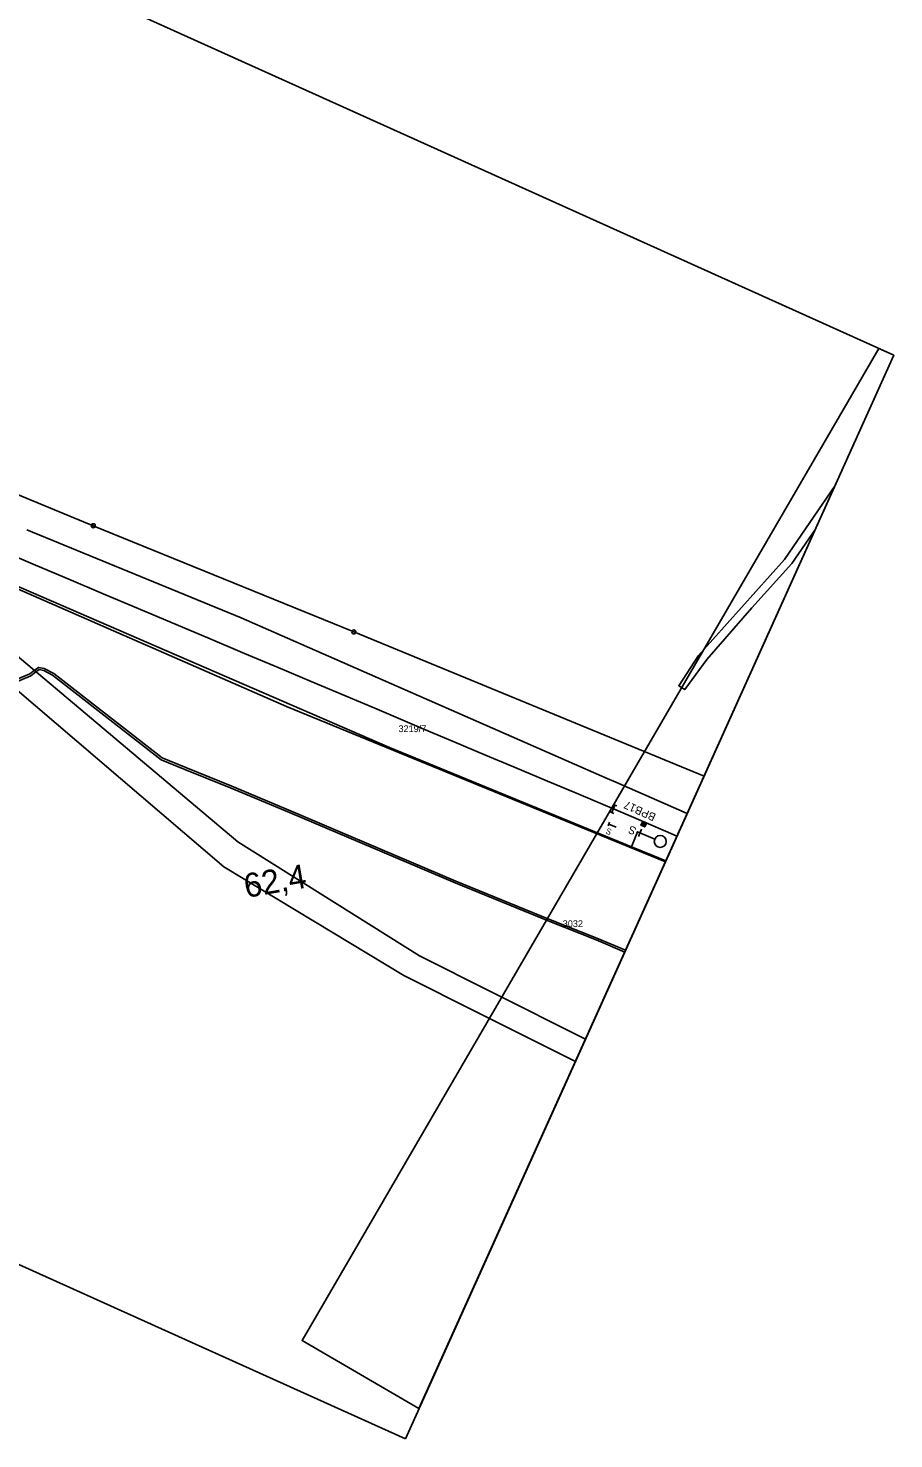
# Model space of a CAD drawing. Extents: x -621716 to -621020, y -1122350 to -1121821.
# Drawn here: x -621236.3 to -621020, y -1122350.4 to -1121998 of the extents above; entities that cross this region are included whole.
import ezdxf

# ---------------------------------------------------------------- set-up
doc = ezdxf.new("R2010")
doc.units = 0
for name, color, linetype in [('hm', 7, 'Continuous'), ('HranDP', 7, 'Continuous'), ('Hranice parcel', 7, 'Continuous'), ('Parcelní čísla', 7, 'Continuous'), ('Rámečky-tisk', 7, 'Continuous'), ('STANICENI NOVE HM', 7, 'Continuous'), ('Vrstva 1', 7, 'Continuous'), ('Vrstva 2', 7, 'Continuous'), ('Vrstva 3', 7, 'Continuous'), ('Vrstva 6', 7, 'Continuous'), ('Věcná břemena k části', 7, 'Continuous'), ('Značky bodu BP', 7, 'Continuous')]:
    doc.layers.add(name, color=color, linetype=linetype)

msp = doc.modelspace()

# ---------------------------------------------------------------- linework, layer by layer
at = {"layer": 'hm'}
for p, q in [((-621236.12, -1122131.3), (-621236.12, -1122131.3)), ((-621143.95, -1122170.24), (-621143.95, -1122170.24))]:
    msp.add_line(p, q, dxfattribs=at)
at = {"layer": 'HranDP'}
for points in [[(-621071.57, -1122194.18), (-621089.46, -1122186.34), (-621091.58, -1122185.41), (-621183.06, -1122145.34), (-621236.6, -1122123.3)], [(-621077.02, -1122206.26), (-621096.79, -1122198.16), (-621171.69, -1122167.46), (-621240.3, -1122137.45)]]:
    msp.add_lwpolyline(points, dxfattribs=at)
at = {"layer": 'Hranice parcel'}
for points in [[(-621316.28, -1121963.73), (-621318.05, -1121968.15), (-621373.38, -1122024.18), (-621378.72, -1122030.05), (-621381.72, -1122035.12), (-621383.2, -1122041.04), (-621383.06, -1122046.37), (-621381.45, -1122051.28), (-621377.34, -1122056.11), (-621371.25, -1122059.79), (-621220, -1122122.28), (-621154.89, -1122148.82), (-621067.38, -1122184.88)], [(-621187.4, -1122207.5), (-621250, -1122154.05), (-621256.5, -1122148.5), (-621279.33, -1122126.02), (-621347.74, -1122094.36), (-621373.17, -1122084.12), (-621407.84, -1122078), (-621413.72, -1122077.04), (-621414.64, -1122076.64)], [(-621039.54, -1122123.11), (-621045.46, -1122131.72), (-621055.41, -1122142.78), (-621066.65, -1122155.68), (-621072.18, -1122163.23), (-621073.7, -1122162.28), (-621068.77, -1122154.75), (-621047.24, -1122130.75), (-621034.62, -1122112.2)], [(-621071.57, -1122194.18), (-621089.46, -1122186.34), (-621091.58, -1122185.41), (-621183.06, -1122145.34), (-621236.6, -1122123.3)], [(-621077.02, -1122206.26), (-621096.79, -1122198.16), (-621171.69, -1122167.46), (-621240.3, -1122137.45)], [(-621247, -1122148.15), (-621183.91, -1122201.29), (-621138.49, -1122229.74), (-621120.6, -1122238.74), (-621097.01, -1122250.61)], [(-621099.51, -1122256.14), (-621123.45, -1122244.15), (-621142.42, -1122234.65), (-621187.4, -1122207.5)]]:
    msp.add_lwpolyline(points, dxfattribs=at)
at = {"layer": 'Rámečky-tisk'}
for points in [[(-621594.3, -1121820.78), (-621716.36, -1122091.54), (-621142.02, -1122350.45)], [(-621142.02, -1122350.45), (-621019.96, -1122079.69), (-621594.3, -1121820.78)], [(-621023.68, -1122078.01), (-621167.83, -1122325.92), (-621138.62, -1122342.9)], [(-621138.62, -1122342.9), (-621019.96, -1122079.69), (-621023.68, -1122078.01)]]:
    msp.add_lwpolyline(points, dxfattribs=at)
at = {"layer": 'Vrstva 1'}
for points in [[(-621085.52, -1122202.49), (-621145.97, -1122177.73), (-621266.9, -1122125.34), (-621335.07, -1122094.53), (-621348.64, -1122088.4), (-621357.58, -1122084.62), (-621357.08, -1122083.45), (-621364.5, -1122080.32), (-621400.77, -1122065), (-621401.81, -1122066.92), (-621406.73, -1122065.04)], [(-621242.46, -1122128.76), (-621234.48, -1122132.13), (-621226.13, -1122135.65), (-621217.53, -1122139.28), (-621208.79, -1122142.96), (-621200.3, -1122146.55), (-621191.38, -1122150.31), (-621182.22, -1122154.18), (-621173.81, -1122157.72), (-621165.57, -1122161.19), (-621156.77, -1122164.91), (-621149.67, -1122167.91), (-621143.22, -1122170.63), (-621137.43, -1122173.08), (-621129.68, -1122176.35), (-621122.01, -1122179.58), (-621114.57, -1122182.71), (-621106.5, -1122186.11), (-621098.7, -1122189.4), (-621092.01, -1122192.21), (-621090.02, -1122193.05), (-621083.15, -1122195.96), (-621075.1, -1122199.44), (-621074.14, -1122199.87)], [(-621083.39, -1122199.04), (-621084.03, -1122198.76), (-621085.52, -1122202.49)], [(-621076.91, -1122206.02), (-621080.17, -1122204.68), (-621085.52, -1122202.49)]]:
    msp.add_lwpolyline(points, dxfattribs=at)
at = {"layer": 'Vrstva 2'}
for p, q in [((-621083, -1122198.12), (-621083.78, -1122199.96)), ((-621083.12, -1122197.06), (-621081.8, -1122196.57)), ((-621083.04, -1122196.89), (-621081.97, -1122196.5)), ((-621083.03, -1122197.16), (-621081.8, -1122196.71)), ((-621082.96, -1122196.72), (-621082.14, -1122196.42)), ((-621082.88, -1122196.55), (-621082.31, -1122196.34)), ((-621082.86, -1122197.24), (-621081.88, -1122196.88)), ((-621082.8, -1122196.38), (-621082.48, -1122196.26)), ((-621082.73, -1122196.21), (-621082.65, -1122196.19)), ((-621082.69, -1122197.32), (-621081.96, -1122197.05)), ((-621082.52, -1122197.4), (-621082.03, -1122197.22)), ((-621082.36, -1122197.48), (-621082.11, -1122197.39)), ((-621079.7, -1122200.6), (-621083.39, -1122199.04))]:
    msp.add_line(p, q, dxfattribs=at)
msp.add_lwpolyline([(-621082.7, -1122196.16), (-621081.75, -1122196.6), (-621082.19, -1122197.55), (-621083.14, -1122197.11)], close=True, dxfattribs=at)
msp.add_lwpolyline([(-621082.7, -1122196.16), (-621081.75, -1122196.6), (-621082.19, -1122197.55), (-621083.14, -1122197.11)], close=True, dxfattribs=at)
msp.add_circle((-621078.32, -1122201.18), 1.5, dxfattribs=at)
at = {"layer": 'Vrstva 3'}
for p, q in [((-621090.87, -1122193.78), (-621089.95, -1122194.16)), ((-621089.64, -1122192.13), (-621090.41, -1122193.97)), ((-621090.1, -1122191.93), (-621089.18, -1122192.32))]:
    msp.add_line(p, q, dxfattribs=at)
at = {"layer": 'Vrstva 6'}
for p, q in [((-621090.97, -1122196.38), (-621091.37, -1122197.3)), ((-621089.36, -1122197.63), (-621091.17, -1122196.84))]:
    msp.add_line(p, q, dxfattribs=at)
at = {"layer": 'Věcná břemena k části'}
msp.add_line((-621087.19, -1122228.82), (-621086.99, -1122228.37), dxfattribs=at)
msp.add_lwpolyline([(-621234.35, -1122158.81), (-621234.74, -1122158.48), (-621235.87, -1122159.33), (-621240.17, -1122161.16), (-621241.08, -1122161.66), (-621240.68, -1122162.01), (-621239.95, -1122161.6), (-621235.61, -1122159.77)], close=True, dxfattribs=at)
msp.add_lwpolyline([(-621086.99, -1122228.37), (-621094.18, -1122225.34), (-621106.18, -1122220.59), (-621129.4, -1122211.1), (-621170.76, -1122193.49), (-621185.38, -1122187.37), (-621196.91, -1122182.72), (-621202.81, -1122180.31), (-621229.89, -1122159.2), (-621232.24, -1122157.96), (-621233.68, -1122157.67), (-621234.74, -1122158.48), (-621234.35, -1122158.81), (-621233.56, -1122158.21), (-621232.4, -1122158.44), (-621230.17, -1122159.62), (-621203.07, -1122180.75), (-621197.09, -1122183.18), (-621185.58, -1122187.83), (-621170.96, -1122193.95), (-621129.6, -1122211.56), (-621106.36, -1122221.05), (-621094.36, -1122225.8), (-621087.19, -1122228.82)], dxfattribs=at)
at = {"layer": 'Značky bodu BP'}
for centre, radius in [((-621220, -1122122.28), 0.5), ((-621220, -1122122.28), 0.0303), ((-621154.89, -1122148.82), 0.5), ((-621154.89, -1122148.82), 0.0303)]:
    msp.add_circle(centre, radius, dxfattribs=at)

# ---------------------------------------------------------------- texts
at = {"layer": 'Parcelní čísla'}
for s, p in [('3219/7', (-621143.74, -1122173.86)), ('3032', (-621102.69, -1122222.58))]:
    msp.add_text(s, height=1.7, dxfattribs=at).set_placement(p)
at = {"layer": 'STANICENI NOVE HM'}
msp.add_text('62,4', height=6, rotation=9.6991, dxfattribs=at).set_placement((-621181.81, -1122215.31))
at = {"layer": 'Vrstva 3'}
for s, p in [('BPB17', (-621079.23, -1122194.37)), ('S', (-621084.1, -1122197.86))]:
    msp.add_text(s, height=2, rotation=155.7341, dxfattribs=at).set_placement(p)
at = {"layer": 'Vrstva 6'}
msp.add_text('S', height=1.5, rotation=336.4373, dxfattribs=at).set_placement((-621092.12, -1122199.11))

doc.saveas('drawing.dxf')
